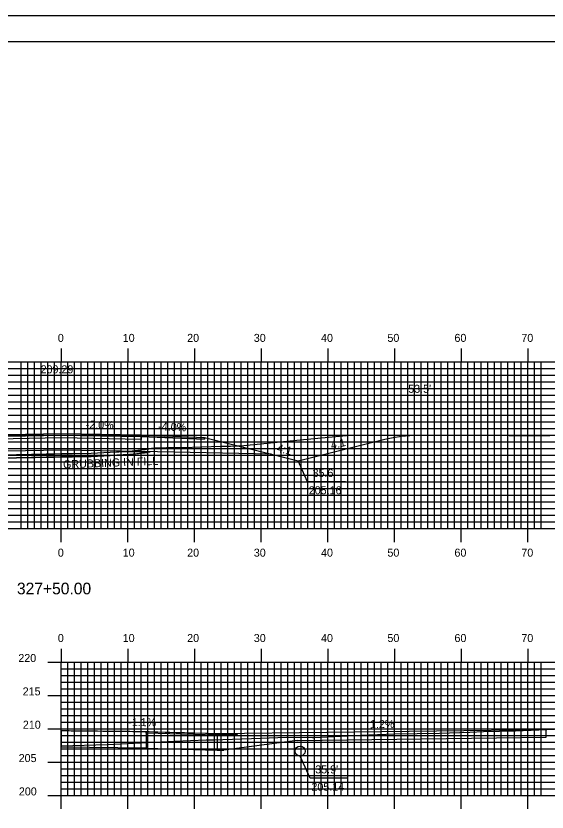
# Model space of a CAD drawing. Extents: x 1821605 to 1821948, y 442591 to 442811.
# Drawn here: x 1821764 to 1821843.6, y 442691.2 to 442810.5 of the extents above; entities that cross this region are included whole.
import ezdxf

# ---------------------------------------------------------------- set-up
doc = ezdxf.new("R2010")
doc.units = 0
for name, color, linetype in [('ANNOTATION', 7, 'Continuous'), ('BORDER', 7, 'Continuous'), ('D_Drainage_Culvert', 7, 'Continuous'), ('D_Roadway_Centerline', 7, 'Continuous'), ('D_Roadway_Centerline_Text', 7, 'Continuous'), ('D_Roadway_Edge_Shoulder', 7, 'Continuous'), ('D_Roadway_Edge_TW', 7, 'Continuous'), ('D_Roadway_Pavement', 7, 'Continuous'), ('D_Roadway_SlopeLines', 7, 'Continuous'), ('D_Roadway_SubGrade', 7, 'Continuous'), ('D_Text_Standard', 7, 'Continuous'), ('GRUBBING IN FILL', 7, 'Continuous'), ('H_V ANNOTATION', 7, 'Continuous'), ('MAJOR', 7, 'Continuous'), ('MINOR', 7, 'Continuous'), ('PLOT BOUNDARY', 7, 'Continuous'), ('S_Roadway_Centerline', 7, 'Continuous')]:
    doc.layers.add(name, color=color, linetype=linetype)

msp = doc.modelspace()

# ---------------------------------------------------------------- linework, layer by layer
at = {"layer": 'ANNOTATION'}
for p, q in [((1821794.15, 442702.93), (1821794.15, 442702.68)), ((1821794.15, 442702.68), (1821794.15, 442700.43)), ((1821843.46, 442702.38), (1821843.46, 442703.53)), ((1821794.15, 442700.43), (1821795.15, 442700.43))]:
    msp.add_line(p, q, dxfattribs=at)
for points in [[(1821813.39, 442740.69), (1821807.7, 442740.69), (1821806.31, 442743.83)], [(1821797.15, 442702.97), (1821797.15, 442702.8), (1821794.15, 442702.77)], [(1821813.79, 442696.24), (1821808.09, 442696.24), (1821806.58, 442699.57)]]:
    msp.add_lwpolyline(points, dxfattribs=at)
at = {"layer": 'BORDER'}
msp.add_lwpolyline([(1821621.14, 442596.67), (1821941.14, 442596.67), (1821941.14, 442806.67), (1821621.14, 442806.67)], close=True, dxfattribs=at)
at = {"layer": 'D_Drainage_Culvert'}
msp.add_circle((1821806.58, 442700.32), 0.75, dxfattribs=at)
at = {"layer": 'D_Roadway_Centerline'}
msp.add_lwpolyline([(1821770.74, 442703.39), (1821770.74, 442703.39), (1821771.97, 442703.38), (1821772.25, 442703.37), (1821772.96, 442703.37), (1821773.11, 442703.36), (1821774.56, 442703.35), (1821775.17, 442703.34), (1821776.23, 442703.33), (1821777.03, 442703.32), (1821777.53, 442703.32), (1821778.1, 442703.31), (1821779.09, 442703.3), (1821780.95, 442703.28), (1821780.96, 442703.28), (1821781.03, 442703.28), (1821781.49, 442703.27), (1821783.51, 442703.25), (1821783.86, 442703.24), (1821783.96, 442703.24), (1821784.76, 442703.21), (1821784.86, 442703.21), (1821786.35, 442703.17), (1821786.89, 442703.15), (1821787.99, 442703.12), (1821788.78, 442703.09), (1821789.26, 442703.08), (1821789.82, 442703.06), (1821790.74, 442703.03), (1821792.7, 442702.98), (1821792.71, 442702.98), (1821792.75, 442702.97), (1821793.05, 442702.97), (1821794.15, 442702.93)], dxfattribs=at)
at = {"layer": 'D_Roadway_Edge_Shoulder'}
for points in [[(1821782.74, 442747.72), (1821792.26, 442747.34), (1821792.26, 442747.09), (1821782.74, 442747.47)], [(1821783.51, 442703.25), (1821794.15, 442702.93), (1821794.15, 442702.68), (1821783.51, 442703)]]:
    msp.add_lwpolyline(points, close=True, dxfattribs=at)
at = {"layer": 'D_Roadway_Edge_TW'}
msp.add_lwpolyline([(1821746.74, 442747.23), (1821746.74, 442747.48), (1821770.74, 442747.96), (1821782.74, 442747.72), (1821782.74, 442747.47), (1821770.74, 442747.71)], close=True, dxfattribs=at)
at = {"layer": 'D_Roadway_Pavement'}
for p, q in [((1821770.74, 442703.39), (1821770.74, 442700.89)), ((1821783.51, 442703.25), (1821783.51, 442700.75)), ((1821806.15, 442701.91), (1821795.15, 442700.43)), ((1821783.51, 442700.75), (1821770.74, 442700.89)), ((1821783.51, 442700.75), (1821794.15, 442700.43))]:
    msp.add_line(p, q, dxfattribs=at)
msp.add_lwpolyline([(1821746.74, 442746.81), (1821746.74, 442747.23), (1821770.74, 442747.71), (1821782.74, 442747.47), (1821782.74, 442747.05), (1821770.74, 442747.29)], close=True, dxfattribs=at)
at = {"layer": 'D_Roadway_SlopeLines'}
for points in [[(1821792.26, 442747.34), (1821806.31, 442743.83)], [(1821806.31, 442743.83), (1821819.28, 442747.07), (1821820.53, 442747.34), (1821821.78, 442747.54), (1821823.03, 442747.65), (1821824.28, 442747.69)]]:
    msp.add_lwpolyline(points, dxfattribs=at)
at = {"layer": 'D_Roadway_SubGrade'}
for p, q in [((1821794.15, 442702.93), (1821843.45, 442703.54)), ((1821806.15, 442701.91), (1821843.46, 442702.38))]:
    msp.add_line(p, q, dxfattribs=at)
msp.add_lwpolyline([(1821740.74, 442747.24), (1821740.74, 442746.99), (1821746.74, 442747.23), (1821770.74, 442747.71), (1821782.74, 442747.47), (1821792.26, 442747.09), (1821792.26, 442747.34), (1821802.31, 442744.83), (1821782.74, 442745.22), (1821770.74, 442745.46), (1821746.74, 442744.98), (1821730.4, 442744.65)], dxfattribs=at)
at = {"layer": 'GRUBBING IN FILL'}
msp.add_lwpolyline([(1821730.4, 442743.83), (1821744.87, 442743.98), (1821752.59, 442744.01), (1821764.07, 442744.29), (1821775.28, 442744.51), (1821780.99, 442744.77), (1821783.23, 442745.03), (1821783.43, 442745.07), (1821783.66, 442745.11), (1821783.97, 442745.17), (1821784.09, 442745.19)], dxfattribs=at)
msp.add_lwpolyline([(1821730.4, 442743.83), (1821744.87, 442743.98), (1821752.59, 442744.01), (1821764.07, 442744.29), (1821775.28, 442744.51), (1821780.99, 442744.77), (1821783.23, 442745.03), (1821783.43, 442745.07), (1821783.66, 442745.11), (1821783.97, 442745.17), (1821784.09, 442745.19)], dxfattribs=at)
for points in [[(1821730.4, 442744.33), (1821737.64, 442744.4), (1821744.87, 442744.48), (1821752.58, 442744.51), (1821758.32, 442744.65), (1821764.06, 442744.79), (1821770.74, 442744.92), (1821770.74, 442744.42), (1821764.07, 442744.29), (1821758.33, 442744.15), (1821752.59, 442744.01), (1821748.73, 442743.99), (1821744.87, 442743.98), (1821737.63, 442743.9), (1821730.4, 442743.83)], [(1821730.4, 442744.33), (1821737.64, 442744.4), (1821744.87, 442744.48), (1821752.58, 442744.51), (1821758.32, 442744.65), (1821764.06, 442744.79), (1821770.74, 442744.92), (1821770.74, 442744.42), (1821764.07, 442744.29), (1821758.33, 442744.15), (1821752.59, 442744.01), (1821748.73, 442743.99), (1821744.87, 442743.98), (1821737.63, 442743.9), (1821730.4, 442743.83)], [(1821770.74, 442744.92), (1821775.26, 442745.01), (1821778.11, 442745.14), (1821780.74, 442745.26), (1821782.74, 442745.22), (1821784.09, 442745.19), (1821783.23, 442745.03), (1821782.11, 442744.9), (1821780.99, 442744.77), (1821778.14, 442744.64), (1821775.28, 442744.51), (1821770.74, 442744.42)], [(1821770.74, 442744.92), (1821775.26, 442745.01), (1821778.11, 442745.14), (1821780.74, 442745.26), (1821782.74, 442745.22), (1821784.09, 442745.19), (1821783.23, 442745.03), (1821782.11, 442744.9), (1821780.99, 442744.77), (1821778.14, 442744.64), (1821775.28, 442744.51), (1821770.74, 442744.42)]]:
    msp.add_lwpolyline(points, close=True, dxfattribs=at)
at = {"layer": 'MAJOR'}
for p, q in [((1821770.74, 442760.67), (1821770.74, 442758.67)), ((1821780.74, 442760.67), (1821780.74, 442758.67)), ((1821790.74, 442760.67), (1821790.74, 442758.67)), ((1821800.74, 442760.67), (1821800.74, 442758.67)), ((1821810.74, 442760.67), (1821810.74, 442758.67)), ((1821820.74, 442760.67), (1821820.74, 442758.67)), ((1821830.74, 442760.67), (1821830.74, 442758.67)), ((1821840.74, 442760.67), (1821840.74, 442758.67)), ((1821630.74, 442758.67), (1821910.74, 442758.67)), ((1821630.74, 442758.67), (1821910.74, 442758.67)), ((1821770.74, 442733.67), (1821770.74, 442758.67)), ((1821780.74, 442733.67), (1821780.74, 442758.67)), ((1821790.74, 442733.67), (1821790.74, 442758.67)), ((1821800.74, 442733.67), (1821800.74, 442758.67)), ((1821810.74, 442733.67), (1821810.74, 442758.67)), ((1821820.74, 442733.67), (1821820.74, 442758.67)), ((1821830.74, 442733.67), (1821830.74, 442758.67)), ((1821840.74, 442733.67), (1821840.74, 442758.67)), ((1821630.74, 442753.67), (1821910.74, 442753.67)), ((1821630.74, 442748.67), (1821910.74, 442748.67)), ((1821630.74, 442743.67), (1821910.74, 442743.67)), ((1821630.74, 442738.67), (1821910.74, 442738.67)), ((1821630.74, 442733.67), (1821910.74, 442733.67)), ((1821630.74, 442733.67), (1821910.74, 442733.67)), ((1821770.74, 442731.66), (1821770.74, 442733.67)), ((1821780.74, 442731.66), (1821780.74, 442733.67)), ((1821790.74, 442731.66), (1821790.74, 442733.67)), ((1821800.74, 442731.66), (1821800.74, 442733.67)), ((1821810.74, 442731.66), (1821810.74, 442733.67)), ((1821820.74, 442731.66), (1821820.74, 442733.67)), ((1821830.74, 442731.66), (1821830.74, 442733.67)), ((1821840.74, 442731.66), (1821840.74, 442733.67)), ((1821770.74, 442715.67), (1821770.74, 442713.67)), ((1821780.74, 442715.67), (1821780.74, 442713.67)), ((1821790.74, 442715.67), (1821790.74, 442713.67)), ((1821800.74, 442715.67), (1821800.74, 442713.67)), ((1821810.74, 442715.67), (1821810.74, 442713.67)), ((1821820.74, 442715.67), (1821820.74, 442713.67)), ((1821830.74, 442715.67), (1821830.74, 442713.67)), ((1821840.74, 442715.67), (1821840.74, 442713.67)), ((1821768.74, 442713.67), (1821770.74, 442713.67)), ((1821770.74, 442713.67), (1821910.74, 442713.67)), ((1821770.74, 442693.67), (1821770.74, 442713.67)), ((1821770.74, 442693.67), (1821770.74, 442713.67)), ((1821770.74, 442713.67), (1821910.74, 442713.67)), ((1821780.74, 442693.67), (1821780.74, 442713.67)), ((1821790.74, 442693.67), (1821790.74, 442713.67)), ((1821800.74, 442693.67), (1821800.74, 442713.67)), ((1821810.74, 442693.67), (1821810.74, 442713.67)), ((1821820.74, 442693.67), (1821820.74, 442713.67)), ((1821830.74, 442693.67), (1821830.74, 442713.67)), ((1821840.74, 442693.67), (1821840.74, 442713.67)), ((1821768.74, 442708.67), (1821770.74, 442708.67)), ((1821770.74, 442708.67), (1821910.74, 442708.67)), ((1821768.74, 442703.67), (1821770.74, 442703.67)), ((1821770.74, 442703.67), (1821910.74, 442703.67)), ((1821768.74, 442698.67), (1821770.74, 442698.67)), ((1821770.74, 442698.67), (1821910.74, 442698.67)), ((1821768.74, 442693.67), (1821770.74, 442693.67)), ((1821770.74, 442693.67), (1821910.74, 442693.67)), ((1821770.74, 442693.67), (1821910.74, 442693.67)), ((1821770.74, 442691.66), (1821770.74, 442693.67)), ((1821780.74, 442691.66), (1821780.74, 442693.67)), ((1821790.74, 442691.66), (1821790.74, 442693.67)), ((1821800.74, 442691.66), (1821800.74, 442693.67)), ((1821810.74, 442691.66), (1821810.74, 442693.67)), ((1821820.74, 442691.66), (1821820.74, 442693.67)), ((1821830.74, 442691.66), (1821830.74, 442693.67)), ((1821840.74, 442691.66), (1821840.74, 442693.67))]:
    msp.add_line(p, q, dxfattribs=at)
at = {"layer": 'MINOR'}
for p, q in [((1821764.74, 442733.67), (1821764.74, 442758.67)), ((1821765.74, 442733.67), (1821765.74, 442758.67)), ((1821766.74, 442733.67), (1821766.74, 442758.67)), ((1821767.74, 442733.67), (1821767.74, 442758.67)), ((1821768.74, 442733.67), (1821768.74, 442758.67)), ((1821769.74, 442733.67), (1821769.74, 442758.67)), ((1821771.74, 442733.67), (1821771.74, 442758.67)), ((1821772.74, 442733.67), (1821772.74, 442758.67)), ((1821773.74, 442733.67), (1821773.74, 442758.67)), ((1821774.74, 442733.67), (1821774.74, 442758.67)), ((1821775.74, 442733.67), (1821775.74, 442758.67)), ((1821776.74, 442733.67), (1821776.74, 442758.67)), ((1821777.74, 442733.67), (1821777.74, 442758.67)), ((1821778.74, 442733.67), (1821778.74, 442758.67)), ((1821779.74, 442733.67), (1821779.74, 442758.67)), ((1821781.74, 442733.67), (1821781.74, 442758.67)), ((1821782.74, 442733.67), (1821782.74, 442758.67)), ((1821783.74, 442733.67), (1821783.74, 442758.67)), ((1821784.74, 442733.67), (1821784.74, 442758.67)), ((1821785.74, 442733.67), (1821785.74, 442758.67)), ((1821786.74, 442733.67), (1821786.74, 442758.67)), ((1821787.74, 442733.67), (1821787.74, 442758.67)), ((1821788.74, 442733.67), (1821788.74, 442758.67)), ((1821789.74, 442733.67), (1821789.74, 442758.67)), ((1821791.74, 442733.67), (1821791.74, 442758.67)), ((1821792.74, 442733.67), (1821792.74, 442758.67)), ((1821793.74, 442733.67), (1821793.74, 442758.67)), ((1821794.74, 442733.67), (1821794.74, 442758.67)), ((1821795.74, 442733.67), (1821795.74, 442758.67)), ((1821796.74, 442733.67), (1821796.74, 442758.67)), ((1821797.74, 442733.67), (1821797.74, 442758.67)), ((1821798.74, 442733.67), (1821798.74, 442758.67)), ((1821799.74, 442733.67), (1821799.74, 442758.67)), ((1821801.74, 442733.67), (1821801.74, 442758.67)), ((1821802.74, 442733.67), (1821802.74, 442758.67)), ((1821803.74, 442733.67), (1821803.74, 442758.67)), ((1821804.74, 442733.67), (1821804.74, 442758.67)), ((1821805.74, 442733.67), (1821805.74, 442758.67)), ((1821806.74, 442733.67), (1821806.74, 442758.67)), ((1821807.74, 442733.67), (1821807.74, 442758.67)), ((1821808.74, 442733.67), (1821808.74, 442758.67)), ((1821809.74, 442733.67), (1821809.74, 442758.67)), ((1821811.74, 442733.67), (1821811.74, 442758.67)), ((1821812.74, 442733.67), (1821812.74, 442758.67)), ((1821813.74, 442733.67), (1821813.74, 442758.67)), ((1821814.74, 442733.67), (1821814.74, 442758.67)), ((1821815.74, 442733.67), (1821815.74, 442758.67)), ((1821816.74, 442733.67), (1821816.74, 442758.67)), ((1821817.74, 442733.67), (1821817.74, 442758.67)), ((1821818.74, 442733.67), (1821818.74, 442758.67)), ((1821819.74, 442733.67), (1821819.74, 442758.67)), ((1821821.74, 442733.67), (1821821.74, 442758.67)), ((1821822.74, 442733.67), (1821822.74, 442758.67)), ((1821823.74, 442733.67), (1821823.74, 442758.67)), ((1821824.74, 442733.67), (1821824.74, 442758.67)), ((1821825.74, 442733.67), (1821825.74, 442758.67)), ((1821826.74, 442733.67), (1821826.74, 442758.67)), ((1821827.74, 442733.67), (1821827.74, 442758.67)), ((1821828.74, 442733.67), (1821828.74, 442758.67)), ((1821829.74, 442733.67), (1821829.74, 442758.67)), ((1821831.74, 442733.67), (1821831.74, 442758.67)), ((1821832.74, 442733.67), (1821832.74, 442758.67)), ((1821833.74, 442733.67), (1821833.74, 442758.67)), ((1821834.74, 442733.67), (1821834.74, 442758.67)), ((1821835.74, 442733.67), (1821835.74, 442758.67)), ((1821836.74, 442733.67), (1821836.74, 442758.67)), ((1821837.74, 442733.67), (1821837.74, 442758.67)), ((1821838.74, 442733.67), (1821838.74, 442758.67)), ((1821839.74, 442733.67), (1821839.74, 442758.67)), ((1821841.74, 442733.67), (1821841.74, 442758.67)), ((1821842.74, 442733.67), (1821842.74, 442758.67)), ((1821630.74, 442757.67), (1821910.74, 442757.67)), ((1821630.74, 442756.67), (1821910.74, 442756.67)), ((1821630.74, 442755.67), (1821910.74, 442755.67)), ((1821630.74, 442754.67), (1821910.74, 442754.67)), ((1821630.74, 442752.67), (1821910.74, 442752.67)), ((1821630.74, 442751.67), (1821910.74, 442751.67)), ((1821630.74, 442750.67), (1821910.74, 442750.67)), ((1821630.74, 442749.67), (1821910.74, 442749.67)), ((1821630.74, 442747.67), (1821910.74, 442747.67)), ((1821630.74, 442746.67), (1821910.74, 442746.67)), ((1821630.74, 442745.67), (1821910.74, 442745.67)), ((1821630.74, 442744.67), (1821910.74, 442744.67)), ((1821630.74, 442742.67), (1821910.74, 442742.67)), ((1821630.74, 442741.67), (1821910.74, 442741.67)), ((1821630.74, 442740.67), (1821910.74, 442740.67)), ((1821630.74, 442739.67), (1821910.74, 442739.67)), ((1821630.74, 442737.67), (1821910.74, 442737.67)), ((1821630.74, 442736.67), (1821910.74, 442736.67)), ((1821630.74, 442735.67), (1821910.74, 442735.67)), ((1821630.74, 442734.67), (1821910.74, 442734.67)), ((1821771.74, 442693.67), (1821771.74, 442713.67)), ((1821772.74, 442693.67), (1821772.74, 442713.67)), ((1821773.74, 442693.67), (1821773.74, 442713.67)), ((1821774.74, 442693.67), (1821774.74, 442713.67)), ((1821775.74, 442693.67), (1821775.74, 442713.67)), ((1821776.74, 442693.67), (1821776.74, 442713.67)), ((1821777.74, 442693.67), (1821777.74, 442713.67)), ((1821778.74, 442693.67), (1821778.74, 442713.67)), ((1821779.74, 442693.67), (1821779.74, 442713.67)), ((1821781.74, 442693.67), (1821781.74, 442713.67)), ((1821782.74, 442693.67), (1821782.74, 442713.67)), ((1821783.74, 442693.67), (1821783.74, 442713.67)), ((1821784.74, 442693.67), (1821784.74, 442713.67)), ((1821785.74, 442693.67), (1821785.74, 442713.67)), ((1821786.74, 442693.67), (1821786.74, 442713.67)), ((1821787.74, 442693.67), (1821787.74, 442713.67)), ((1821788.74, 442693.67), (1821788.74, 442713.67)), ((1821789.74, 442693.67), (1821789.74, 442713.67)), ((1821791.74, 442693.67), (1821791.74, 442713.67)), ((1821792.74, 442693.67), (1821792.74, 442713.67)), ((1821793.74, 442693.67), (1821793.74, 442713.67)), ((1821794.74, 442693.67), (1821794.74, 442713.67)), ((1821795.74, 442693.67), (1821795.74, 442713.67)), ((1821796.74, 442693.67), (1821796.74, 442713.67)), ((1821797.74, 442693.67), (1821797.74, 442713.67)), ((1821798.74, 442693.67), (1821798.74, 442713.67)), ((1821799.74, 442693.67), (1821799.74, 442713.67)), ((1821801.74, 442693.67), (1821801.74, 442713.67)), ((1821802.74, 442693.67), (1821802.74, 442713.67)), ((1821803.74, 442693.67), (1821803.74, 442713.67)), ((1821804.74, 442693.67), (1821804.74, 442713.67)), ((1821805.74, 442693.67), (1821805.74, 442713.67)), ((1821806.74, 442693.67), (1821806.74, 442713.67)), ((1821807.74, 442693.67), (1821807.74, 442713.67)), ((1821808.74, 442693.67), (1821808.74, 442713.67)), ((1821809.74, 442693.67), (1821809.74, 442713.67)), ((1821811.74, 442693.67), (1821811.74, 442713.67)), ((1821812.74, 442693.67), (1821812.74, 442713.67)), ((1821813.74, 442693.67), (1821813.74, 442713.67)), ((1821814.74, 442693.67), (1821814.74, 442713.67)), ((1821815.74, 442693.67), (1821815.74, 442713.67)), ((1821816.74, 442693.67), (1821816.74, 442713.67)), ((1821817.74, 442693.67), (1821817.74, 442713.67)), ((1821818.74, 442693.67), (1821818.74, 442713.67)), ((1821819.74, 442693.67), (1821819.74, 442713.67)), ((1821821.74, 442693.67), (1821821.74, 442713.67)), ((1821822.74, 442693.67), (1821822.74, 442713.67)), ((1821823.74, 442693.67), (1821823.74, 442713.67)), ((1821824.74, 442693.67), (1821824.74, 442713.67)), ((1821825.74, 442693.67), (1821825.74, 442713.67)), ((1821826.74, 442693.67), (1821826.74, 442713.67)), ((1821827.74, 442693.67), (1821827.74, 442713.67)), ((1821828.74, 442693.67), (1821828.74, 442713.67)), ((1821829.74, 442693.67), (1821829.74, 442713.67)), ((1821831.74, 442693.67), (1821831.74, 442713.67)), ((1821832.74, 442693.67), (1821832.74, 442713.67)), ((1821833.74, 442693.67), (1821833.74, 442713.67)), ((1821834.74, 442693.67), (1821834.74, 442713.67)), ((1821835.74, 442693.67), (1821835.74, 442713.67)), ((1821836.74, 442693.67), (1821836.74, 442713.67)), ((1821837.74, 442693.67), (1821837.74, 442713.67)), ((1821838.74, 442693.67), (1821838.74, 442713.67)), ((1821839.74, 442693.67), (1821839.74, 442713.67)), ((1821841.74, 442693.67), (1821841.74, 442713.67)), ((1821842.74, 442693.67), (1821842.74, 442713.67)), ((1821770.74, 442712.67), (1821910.74, 442712.67)), ((1821770.74, 442712.67), (1821772.75, 442712.67)), ((1821770.74, 442711.67), (1821910.74, 442711.67)), ((1821770.74, 442711.67), (1821772.75, 442711.67)), ((1821770.74, 442710.67), (1821910.74, 442710.67)), ((1821770.74, 442710.67), (1821772.75, 442710.67)), ((1821770.74, 442709.67), (1821910.74, 442709.67)), ((1821770.74, 442709.67), (1821772.75, 442709.67)), ((1821770.74, 442707.67), (1821910.74, 442707.67)), ((1821770.74, 442707.67), (1821772.75, 442707.67)), ((1821770.74, 442706.67), (1821910.74, 442706.67)), ((1821770.74, 442706.67), (1821772.75, 442706.67)), ((1821770.74, 442705.67), (1821910.74, 442705.67)), ((1821770.74, 442705.67), (1821772.75, 442705.67)), ((1821770.74, 442704.67), (1821910.74, 442704.67)), ((1821770.74, 442704.67), (1821772.75, 442704.67)), ((1821770.74, 442702.67), (1821910.74, 442702.67)), ((1821770.74, 442702.67), (1821772.75, 442702.67)), ((1821770.74, 442701.67), (1821910.74, 442701.67)), ((1821770.74, 442701.67), (1821772.75, 442701.67)), ((1821770.74, 442700.67), (1821910.74, 442700.67)), ((1821770.74, 442700.67), (1821772.75, 442700.67)), ((1821770.74, 442699.67), (1821910.74, 442699.67)), ((1821770.74, 442699.67), (1821772.75, 442699.67)), ((1821770.74, 442697.67), (1821910.74, 442697.67)), ((1821770.74, 442697.67), (1821772.75, 442697.67)), ((1821770.74, 442696.67), (1821910.74, 442696.67)), ((1821770.74, 442696.67), (1821772.75, 442696.67)), ((1821770.74, 442695.67), (1821910.74, 442695.67)), ((1821770.74, 442695.67), (1821772.75, 442695.67)), ((1821770.74, 442694.67), (1821910.74, 442694.67)), ((1821770.74, 442694.67), (1821772.75, 442694.67))]:
    msp.add_line(p, q, dxfattribs=at)
at = {"layer": 'PLOT BOUNDARY'}
msp.add_lwpolyline([(1821604.96, 442590.55), (1821944.96, 442590.55), (1821944.96, 442810.55), (1821604.96, 442810.55)], close=True, dxfattribs=at)
at = {"layer": 'S_Roadway_Centerline'}
for points in [[(1821752.58, 442744.51), (1821764.06, 442744.79), (1821775.26, 442745.01), (1821780.95, 442745.27), (1821783.16, 442745.52), (1821783.34, 442745.56), (1821783.57, 442745.6), (1821783.88, 442745.66), (1821784.3, 442745.74), (1821784.73, 442745.81), (1821786.56, 442745.82), (1821789, 442745.83), (1821794.69, 442746.02), (1821796.13, 442746.06), (1821796.68, 442746.08), (1821796.95, 442746.09), (1821797.1, 442746.09), (1821797.2, 442746.09), (1821797.27, 442746.1), (1821797.32, 442746.1), (1821797.36, 442746.1), (1821797.39, 442746.1), (1821797.41, 442746.1), (1821797.43, 442746.1), (1821797.44, 442746.1), (1821797.63, 442746.1), (1821799.07, 442746.25), (1821800.14, 442746.35), (1821807.07, 442747.02), (1821814.1, 442747.7), (1821814.15, 442747.7), (1821814.38, 442747.7), (1821820.7, 442747.7), (1821831.81, 442747.68), (1821843.99, 442747.57)], [(1821770.74, 442701.1), (1821777.69, 442701.3), (1821787.79, 442701.8), (1821792.5, 442701.99), (1821793.62, 442702.02), (1821800.69, 442702.26), (1821804.51, 442702.4), (1821808.43, 442702.37), (1821808.62, 442702.37), (1821816.87, 442702.77), (1821820.8, 442702.88), (1821827.49, 442703.02), (1821832.02, 442703.13), (1821834.08, 442703.23), (1821838.89, 442703.37), (1821842.36, 442703.5), (1821849.46, 442703.8)]]:
    msp.add_lwpolyline(points, dxfattribs=at)

# ---------------------------------------------------------------- texts
at = {"layer": 'ANNOTATION'}
for s, rotation, p in [('-2.0%', 358.8542, (1821774.43, 442748.68)), ('-4.0%', 357.7094, (1821785.29, 442748.42)), ('4:1', 14.0362, (1821811.33, 442745.56)), ('4:1', 345.9638, (1821803.01, 442745.23)), ('-1.1%', 359.3672, (1821780.81, 442704.08)), ('1.2%', 0.7083, (1821817.06, 442703.75))]:
    msp.add_text(s, height=1.2, rotation=rotation, dxfattribs=at).set_placement(p)
for s, p in [("35.6'", (1821808.45, 442741.42)), ('205.16', (1821807.88, 442738.82)), ("35.9'", (1821808.85, 442696.97)), ('205.14', (1821808.28, 442694.37))]:
    msp.add_text(s, height=1.2, dxfattribs=at).set_placement(p)
at = {"layer": 'D_Roadway_Centerline'}
for s, p in [('C', (1821770.74, 442747.96)), ('L', (1821770.74, 442747.95))]:
    msp.add_text(s, height=0.0146, dxfattribs=at).set_placement(p)
at = {"layer": 'D_Roadway_Centerline_Text'}
msp.add_text('209.29', height=1.2, dxfattribs=at).set_placement((1821767.68, 442756.96))
at = {"layer": 'D_Text_Standard'}
msp.add_text("53.5'", height=1.2, dxfattribs=at).set_placement((1821822.79, 442754.04))
at = {"layer": 'GRUBBING IN FILL'}
msp.add_text('GRUBBING IN FILL', height=1.2, rotation=2.1934, dxfattribs=at).set_placement((1821771.07, 442742.69))
at = {"layer": 'H_V ANNOTATION'}
for s, height, p in [('0', 1.2, (1821770.26, 442761.67)), ('10', 1.2, (1821779.99, 442761.67)), ('20', 1.2, (1821789.65, 442761.67)), ('30', 1.2, (1821799.64, 442761.67)), ('40', 1.2, (1821809.72, 442761.67)), ('50', 1.2, (1821819.67, 442761.67)), ('60', 1.2, (1821829.72, 442761.67)), ('70', 1.2, (1821839.75, 442761.67)), ('0', 1.2, (1821770.26, 442729.47)), ('10', 1.2, (1821779.99, 442729.47)), ('20', 1.2, (1821789.65, 442729.47)), ('30', 1.2, (1821799.64, 442729.47)), ('40', 1.2, (1821809.72, 442729.47)), ('50', 1.2, (1821819.67, 442729.47)), ('60', 1.2, (1821829.72, 442729.47)), ('70', 1.2, (1821839.75, 442729.47)), ('327+50.00', 1.75, (1821764.13, 442723.82)), ('0', 1.2, (1821770.26, 442716.67)), ('10', 1.2, (1821779.99, 442716.67)), ('20', 1.2, (1821789.65, 442716.67)), ('30', 1.2, (1821799.64, 442716.67)), ('40', 1.2, (1821809.72, 442716.67)), ('50', 1.2, (1821819.67, 442716.67)), ('60', 1.2, (1821829.72, 442716.67)), ('70', 1.2, (1821839.75, 442716.67)), ('220', 1.2, (1821764.34, 442713.67)), ('215', 1.2, (1821764.99, 442708.67)), ('210', 1.2, (1821765.02, 442703.67)), ('205', 1.2, (1821764.39, 442698.67)), ('200', 1.2, (1821764.42, 442693.67))]:
    msp.add_text(s, height=height, dxfattribs=at).set_placement(p)
at = {"layer": 'MAJOR'}
msp.add_text('-', height=0.012, dxfattribs=at).set_placement((1821770.73, 442693.67))

doc.saveas('drawing.dxf')
